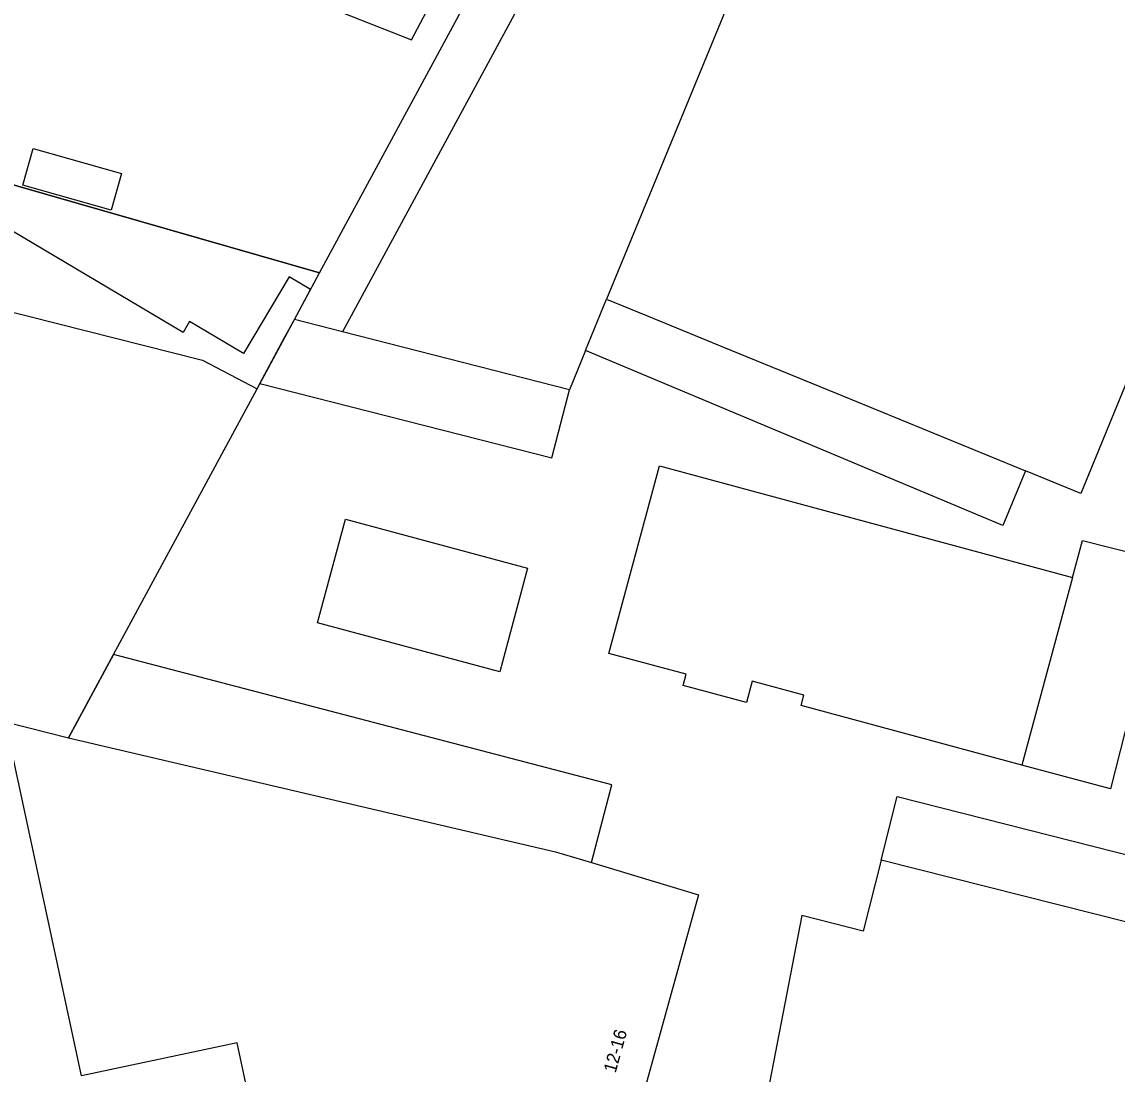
# Model space of a CAD drawing. Extents: x 160557 to 161245, y 385330 to 386505.
# Drawn here: x 160833.2 to 160919, y 385649.9 to 385732.3 of the extents above; entities that cross this region are included whole.
import ezdxf

# ---------------------------------------------------------------- set-up
doc = ezdxf.new("R2010")
doc.units = 0
for name, color, linetype in [('IMGEO_Muur', 7, 'Continuous'), ('IMGEO_Pand', 7, 'Continuous'), ('IMGEO_Pand_nummerreeks', 7, 'Continuous'), ('IMGEO_Pand_overbouw', 7, 'Continuous'), ('IMGEO_Parkeervlak_open', 7, 'Continuous'), ('IMGEO_Rijbaan_lokaal_open', 7, 'Continuous'), ('IMGEO_Voetpad_open', 7, 'Continuous')]:
    doc.layers.add(name, color=color, linetype=linetype)

msp = doc.modelspace()

# ---------------------------------------------------------------- linework, layer by layer
at = {"layer": 'IMGEO_Muur'}
for points in [[(160856.562, 385712.649), (160828.176, 385720.801)], [(160854.587, 385708.993), (160856.562, 385712.649)], [(160851.659, 385703.57), (160854.587, 385708.993)]]:
    msp.add_lwpolyline(points, dxfattribs=at)
at = {"layer": 'IMGEO_Pand'}
for points in [[(160881.514, 385750.473), (160881.359, 385750.556), (160881.058, 385750), (160878.98, 385746.159), (160858.351, 385708.032)], [(160856.532, 385739.441), (160855.165, 385740.013), (160852.609, 385735.322), (160863.75, 385730.906), (160866.142, 385735.422)], [(160889.389, 385735.728), (160879.047, 385710.592)], [(160931.608, 385732.931), (160924.649, 385715.965), (160916.201, 385695.359), (160911.867, 385697.136)], [(160841.044, 385720.441), (160840.226, 385717.554), (160833.299, 385719.517), (160834.117, 385722.403), (160841.044, 385720.441)], [(160818.265, 385719.655), (160815.584, 385714.965), (160824.547, 385711.575), (160847.383, 385705.807), (160851.659, 385703.57)], [(160877.384, 385706.554), (160879.047, 385710.592)], [(160879.047, 385710.592), (160882.751, 385709.074), (160888.205, 385706.838), (160897.603, 385702.985), (160911.867, 385697.136)], [(160876.125, 385703.495), (160858.351, 385708.032)], [(160877.384, 385706.554), (160876.125, 385703.495)], [(160840.418, 385682.754), (160851.659, 385703.57)], [(160911.571, 385674.088), (160894.274, 385678.752), (160894.492, 385679.56), (160890.46, 385680.648), (160890.01, 385678.977), (160885.035, 385680.319), (160885.271, 385681.194), (160879.228, 385682.824), (160883.192, 385697.527), (160915.534, 385688.79)], [(160915.534, 385688.79), (160911.571, 385674.088)], [(160840.418, 385682.754), (160836.882, 385676.206)], [(160831.957, 385677.464), (160836.882, 385676.206)], [(160837.913, 385649.731), (160831.957, 385677.464)], [(160836.882, 385676.206), (160875.046, 385667.287), (160877.848, 385666.443)], [(160900.548, 385666.641), (160899.134, 385661.067), (160894.335, 385662.283), (160891.53, 385647.689), (160890.585, 385642.778)], [(160938.493, 385657.051), (160930.406, 385659.095), (160928.995, 385653.511), (160921.278, 385655.462), (160922.689, 385661.046), (160900.548, 385666.641)], [(160877.848, 385666.443), (160886.253, 385663.911), (160879.468, 385639.494), (160883.291, 385638.462), (160882.614, 385635.957)], [(160882.614, 385635.957), (160878.759, 385636.941), (160867.447, 385640.094), (160867.321, 385639.572), (160859.358, 385637.818), (160858.199, 385643.077), (160852.372, 385641.675), (160850.09, 385652.328), (160837.913, 385649.731)]]:
    msp.add_lwpolyline(points, dxfattribs=at)
at = {"layer": 'IMGEO_Pand_overbouw'}
msp.add_lwpolyline([(160837.913, 385649.731), (160831.957, 385677.464), (160836.882, 385676.206), (160840.418, 385682.754), (160851.659, 385703.57), (160851.886, 385703.991), (160853.793, 385707.522), (160854.587, 385708.993), (160855.857, 385711.343), (160854.163, 385712.349), (160850.589, 385706.33), (160846.376, 385708.832), (160845.865, 385707.972), (160824.111, 385720.889)], dxfattribs=at)
at = {"layer": 'IMGEO_Parkeervlak_open'}
for points in [[(160911.867, 385697.136), (160910.077, 385692.862), (160877.384, 385706.554)], [(160851.886, 385703.991), (160874.761, 385698.152), (160876.125, 385703.495)], [(160872.853, 385689.524), (160870.669, 385681.391), (160856.405, 385685.222), (160858.588, 385693.354), (160872.853, 385689.524)], [(160915.534, 385688.79), (160916.316, 385691.691), (160923.046, 385689.973)], [(160923.046, 385689.973), (160918.514, 385672.216), (160911.571, 385674.088)], [(160900.548, 385666.641), (160901.809, 385671.613), (160934.332, 385663.363), (160940.041, 385685.612)], [(160877.848, 385666.443), (160879.442, 385672.524), (160840.418, 385682.754)]]:
    msp.add_lwpolyline(points, dxfattribs=at)
at = {"layer": 'IMGEO_Rijbaan_lokaal_open'}
for points in [[(160828.176, 385720.801), (160856.562, 385712.649)], [(160854.587, 385708.993), (160856.562, 385712.649)], [(160851.886, 385703.991), (160854.587, 385708.993)], [(160851.659, 385703.57), (160851.886, 385703.991)]]:
    msp.add_lwpolyline(points, dxfattribs=at)
at = {"layer": 'IMGEO_Voetpad_open'}
for points in [[(160856.562, 385712.649), (160882.401, 385760.458)], [(160858.351, 385708.032), (160854.587, 385708.993)]]:
    msp.add_lwpolyline(points, dxfattribs=at)

# ---------------------------------------------------------------- texts
at = {"layer": 'IMGEO_Pand_nummerreeks'}
msp.add_text('12-16', height=1, rotation=74.47305, dxfattribs=at).set_placement((160879.746, 385649.908))

doc.saveas('drawing.dxf')
